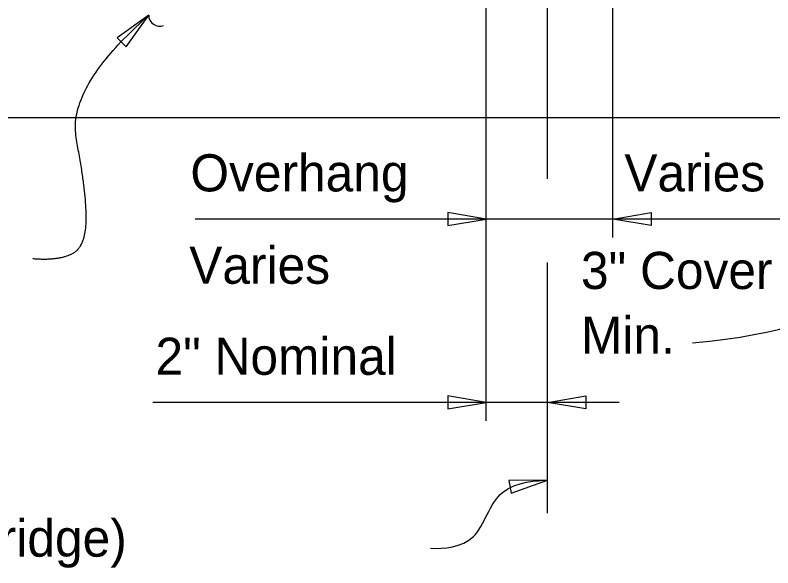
# Model space of a CAD drawing. Extents: x 21652.5 to 21723.2, y 56079.2 to 56117.9.
# Drawn here: x 21680.81 to 21684.922, y 56098.687 to 56101.689 of the extents above; entities that cross this region are included whole.
import ezdxf

# ---------------------------------------------------------------- set-up
doc = ezdxf.new("R2010")
doc.units = 0
for name, color, linetype in [('Dimension', 7, 'Continuous'), ('ExistSuperStruct', 7, 'Continuous'), ('TextStructures', 7, 'Continuous')]:
    doc.layers.add(name, color=color, linetype=linetype)

msp = doc.modelspace()

# ---------------------------------------------------------------- linework, layer by layer
at = {"layer": 'Dimension'}
for p, q in [((21683.3666, 56099.485), (21683.3666, 56104.0496)), ((21683.6999, 56100.7992), (21683.6999, 56103.9172)), ((21684.053, 56100.4813), (21684.053, 56103.7938)), ((21683.9565, 56100.5813), (21681.7863, 56100.5813)), ((21685.6675, 56100.5813), (21682.2191, 56100.5813)), ((21683.6999, 56098.9833), (21683.6999, 56100.3451)), ((21683.6999, 56099.8235), (21683.6999, 56099.8697)), ((21684.0876, 56099.585), (21681.5577, 56099.585))]:
    msp.add_line(p, q, dxfattribs=at)
for points in [[(21681.5355, 56101.6882), (21681.3636, 56101.5656), (21681.4135, 56101.5158)], [(21683.3666, 56100.5811), (21683.1583, 56100.6164), (21683.1583, 56100.5459)], [(21684.053, 56100.5811), (21684.2613, 56100.6164), (21684.2613, 56100.5459)], [(21683.3666, 56099.5849), (21683.1583, 56099.6202), (21683.1583, 56099.5496)], [(21683.6999, 56099.585), (21683.9081, 56099.6203), (21683.9081, 56099.5497)], [(21683.7, 56099.1636), (21683.4888, 56099.1613), (21683.5013, 56099.0919)]]:
    msp.add_lwpolyline(points, close=True, dxfattribs=at)
msp.add_arc((21681.5945, 56101.688), 0.0596, 179.2799, 291.0071, dxfattribs=at)
for points, degree in [([(21680.9059, 56100.3668), (21681.0419, 56100.3548), (21681.1959, 56100.4309), (21681.1959, 56100.7371), (21681.0885, 56101.2941), (21681.5355, 56101.6882)], 2), ([(21684.4868, 56099.9083), (21685.4982, 56100.0044), (21685.4247, 56100.6104), (21685.4247, 56100.6681), (21685.3925, 56100.6263), (21685.3781, 56100.6038), (21685.3702, 56100.5434), (21685.5107, 56100.4806)], 3), ([(21683.0642, 56098.793), (21683.1355, 56098.7913), (21683.3355, 56098.7997), (21683.4057, 56099.1541), (21683.6497, 56099.16), (21683.7, 56099.1636)], 3)]:
    msp.add_open_spline(points, degree=degree, dxfattribs=at)
at = {"layer": 'ExistSuperStruct'}
msp.add_line((21679.5999, 56101.1329), (21685.053, 56101.1329), dxfattribs=at)

# ---------------------------------------------------------------- texts
at = {"layer": 'TextStructures'}
for s, p in [('Overhang', (21681.7612, 56100.7314)), ('Varies', (21684.1164, 56100.7314)), ('Varies', (21681.755, 56100.2298)), ('3" Cover ', (21683.881, 56100.2013)), ('Min.', (21683.881, 56099.8493)), ('2" Nominal', (21681.5718, 56099.7352)), ('Control Line (Projected from Bridge)', (21677.1007, 56098.7476))]:
    msp.add_text(s, height=0.2016, dxfattribs=at).set_placement(p)

doc.saveas('drawing.dxf')
